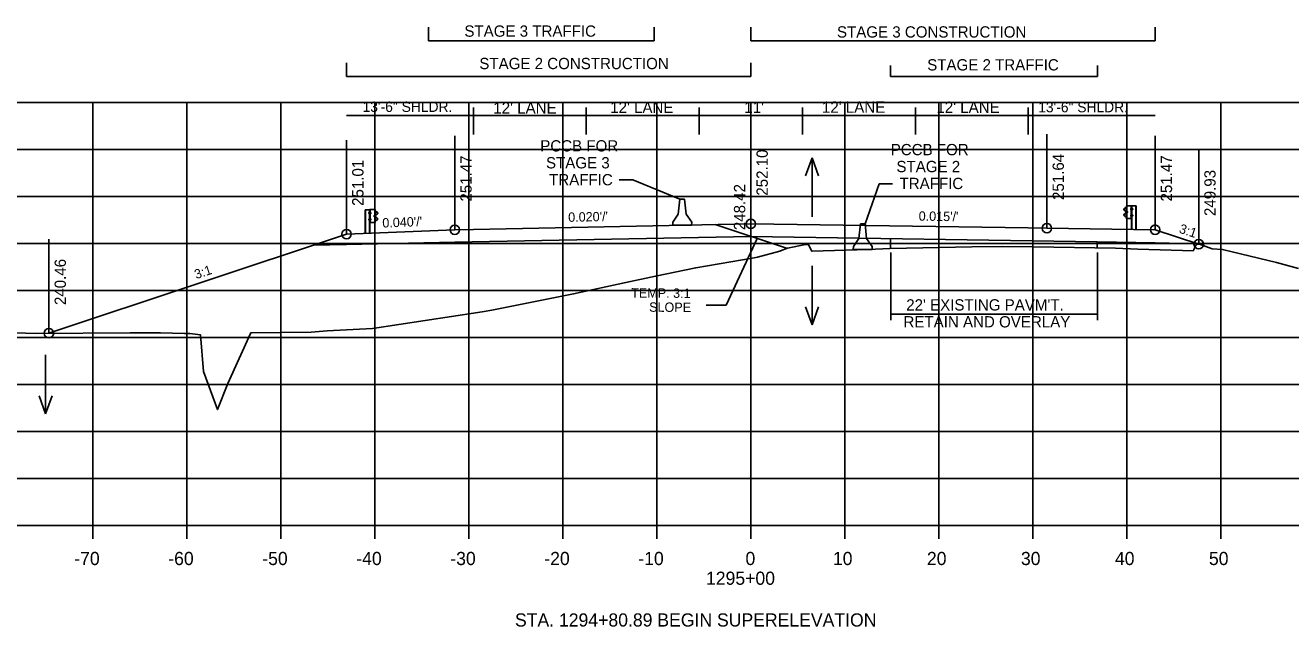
# Model space of a CAD drawing. Extents: x 1342547 to 1344156, y -1532351 to -1517216.
# Drawn here: x 1342625.7 to 1342760.3, y -1520821.7 to -1520757.7 of the extents above; entities that cross this region are included whole.
import ezdxf

# ---------------------------------------------------------------- set-up
doc = ezdxf.new("R2010")
doc.units = 0
for name, color, linetype in [('R_Alt Surface', 7, 'Continuous'), ('R_Axis', 7, 'Continuous'), ('R_Axis Annot', 7, 'Continuous'), ('R_Draft', 7, 'Continuous'), ('R_Exist Surface', 7, 'Continuous'), ('R_Fin Surface', 7, 'Continuous'), ('R_Grid', 7, 'Continuous'), ('R_MOT', 7, 'Continuous'), ('R_No Plot', 7, 'Continuous'), ('R_Water', 7, 'Continuous'), ('R_Xsect Elev', 7, 'Continuous'), ('R_Xsect Slope', 7, 'Continuous')]:
    doc.layers.add(name, color=color, linetype=linetype)

msp = doc.modelspace()

# ---------------------------------------------------------------- linework, layer by layer
at = {"layer": 'R_Alt Surface'}
msp.add_line((1342739.71, -1520780.7), (1342702.87, -1520780.13), dxfattribs=at)
for points in [[(1342659.87, -1520780.99), (1342671.37, -1520780.76), (1342702.87, -1520780.13)], [(1342745.87, -1520780.82), (1342739.71, -1520780.7)], [(1342745.87, -1520780.82), (1342750.33, -1520780.91)], [(1342656.34, -1520781.06), (1342659.87, -1520780.99)]]:
    msp.add_lwpolyline(points, dxfattribs=at)
at = {"layer": 'R_Axis'}
for p, q in [((1342562.87, -1520810.9), (1342842.87, -1520810.9)), ((1342632.87, -1520812.3), (1342632.87, -1520810.9)), ((1342642.87, -1520812.3), (1342642.87, -1520810.9)), ((1342652.87, -1520812.3), (1342652.87, -1520810.9)), ((1342662.87, -1520812.3), (1342662.87, -1520810.9)), ((1342672.87, -1520812.3), (1342672.87, -1520810.9)), ((1342682.87, -1520812.3), (1342682.87, -1520810.9)), ((1342692.87, -1520812.3), (1342692.87, -1520810.9)), ((1342702.87, -1520812.3), (1342702.87, -1520810.9)), ((1342712.87, -1520812.3), (1342712.87, -1520810.9)), ((1342722.87, -1520812.3), (1342722.87, -1520810.9)), ((1342732.87, -1520812.3), (1342732.87, -1520810.9)), ((1342742.87, -1520812.3), (1342742.87, -1520810.9)), ((1342752.87, -1520812.3), (1342752.87, -1520810.9))]:
    msp.add_line(p, q, dxfattribs=at)
at = {"layer": 'R_Draft'}
for p, q in [((1342668.58, -1520759.31), (1342668.58, -1520757.88)), ((1342692.58, -1520759.31), (1342692.58, -1520757.88)), ((1342702.87, -1520759.31), (1342702.87, -1520757.88)), ((1342745.87, -1520759.31), (1342745.87, -1520757.88)), ((1342692.58, -1520759.31), (1342668.58, -1520759.31)), ((1342745.87, -1520759.31), (1342702.87, -1520759.31)), ((1342659.86, -1520763.11), (1342659.86, -1520761.67)), ((1342702.87, -1520763.11), (1342702.87, -1520761.67)), ((1342717.73, -1520763.11), (1342717.73, -1520761.96)), ((1342739.73, -1520763.11), (1342739.73, -1520761.96)), ((1342702.87, -1520763.11), (1342659.86, -1520763.11)), ((1342739.73, -1520763.11), (1342717.73, -1520763.11)), ((1342661.86, -1520777.29), (1342661.86, -1520779.8)), ((1342661.89, -1520777.29), (1342661.89, -1520779.8)), ((1342662.31, -1520777.59), (1342662.26, -1520777.59)), ((1342662.26, -1520777.7), (1342662.26, -1520777.6)), ((1342662.31, -1520777.62), (1342662.26, -1520777.62)), ((1342662.31, -1520777.68), (1342662.26, -1520777.68)), ((1342662.31, -1520777.71), (1342662.26, -1520777.71)), ((1342662.31, -1520777.68), (1342662.27, -1520777.68)), ((1342662.38, -1520777.28), (1342662.31, -1520777.29)), ((1342662.31, -1520777.71), (1342662.31, -1520777.59)), ((1342662.35, -1520779.8), (1342662.35, -1520777.28)), ((1342662.38, -1520777.28), (1342662.38, -1520777.28)), ((1342662.44, -1520777.65), (1342662.38, -1520777.65)), ((1342662.39, -1520777.59), (1342662.44, -1520777.59)), ((1342662.39, -1520777.72), (1342662.44, -1520777.72)), ((1342662.44, -1520777.59), (1342662.44, -1520777.72)), ((1342662.81, -1520778.02), (1342662.81, -1520777.92)), ((1342662.87, -1520777.91), (1342662.82, -1520777.91)), ((1342662.87, -1520777.94), (1342662.82, -1520777.94)), ((1342662.87, -1520778), (1342662.82, -1520778)), ((1342662.87, -1520778.03), (1342662.82, -1520778.03)), ((1342662.87, -1520778), (1342662.83, -1520778)), ((1342662.87, -1520778.03), (1342662.87, -1520777.91)), ((1342662.88, -1520778.65), (1342662.88, -1520777.29)), ((1342663.03, -1520777.5), (1342662.91, -1520777.44)), ((1342663.01, -1520777.52), (1342662.92, -1520777.47)), ((1342662.92, -1520778.03), (1342662.92, -1520777.9)), ((1342662.94, -1520778.03), (1342662.95, -1520777.9)), ((1342663.12, -1520778.2), (1342662.96, -1520778.11)), ((1342662.97, -1520777.83), (1342663.14, -1520777.73)), ((1342662.98, -1520777.85), (1342663.15, -1520777.75)), ((1342663.13, -1520778.18), (1342662.98, -1520778.09)), ((1342663.14, -1520777.62), (1342663.01, -1520777.52)), ((1342663.16, -1520777.6), (1342663.03, -1520777.5)), ((1342742.57, -1520777.19), (1342742.7, -1520777.08)), ((1342742.74, -1520777.44), (1342742.57, -1520777.33)), ((1342742.69, -1520778.03), (1342742.57, -1520777.92)), ((1342742.58, -1520777.2), (1342742.71, -1520777.1)), ((1342742.76, -1520777.41), (1342742.58, -1520777.31)), ((1342742.71, -1520778.02), (1342742.58, -1520777.91)), ((1342742.59, -1520777.77), (1342742.75, -1520777.67)), ((1342742.61, -1520777.79), (1342742.76, -1520777.69)), ((1342742.81, -1520778.09), (1342742.69, -1520778.03)), ((1342742.7, -1520777.08), (1342742.81, -1520777.02)), ((1342742.71, -1520777.1), (1342742.8, -1520777.05)), ((1342742.81, -1520778.07), (1342742.71, -1520778.02)), ((1342742.78, -1520777.62), (1342742.78, -1520777.48)), ((1342742.8, -1520777.61), (1342742.8, -1520777.48)), ((1342742.84, -1520778.23), (1342742.84, -1520776.87)), ((1342742.85, -1520777.62), (1342742.85, -1520777.49)), ((1342742.85, -1520777.49), (1342742.9, -1520777.49)), ((1342742.85, -1520777.52), (1342742.9, -1520777.52)), ((1342742.85, -1520777.59), (1342742.9, -1520777.59)), ((1342742.85, -1520777.59), (1342742.9, -1520777.59)), ((1342742.85, -1520777.62), (1342742.9, -1520777.62)), ((1342742.91, -1520777.6), (1342742.91, -1520777.51)), ((1342743.33, -1520777.17), (1342743.28, -1520777.17)), ((1342743.28, -1520777.17), (1342743.28, -1520777.3)), ((1342743.33, -1520777.3), (1342743.28, -1520777.3)), ((1342743.28, -1520777.98), (1342743.28, -1520777.86)), ((1342743.28, -1520777.86), (1342743.33, -1520777.86)), ((1342743.28, -1520777.98), (1342743.33, -1520777.98)), ((1342743.29, -1520777.24), (1342743.34, -1520777.24)), ((1342743.29, -1520777.92), (1342743.34, -1520777.92)), ((1342743.34, -1520776.87), (1342743.35, -1520776.87)), ((1342743.34, -1520776.87), (1342743.41, -1520776.87)), ((1342743.37, -1520779.38), (1342743.37, -1520776.87)), ((1342743.41, -1520777.29), (1342743.41, -1520777.17)), ((1342743.41, -1520777.17), (1342743.46, -1520777.17)), ((1342743.41, -1520777.2), (1342743.46, -1520777.2)), ((1342743.41, -1520777.26), (1342743.45, -1520777.26)), ((1342743.41, -1520777.26), (1342743.46, -1520777.26)), ((1342743.41, -1520777.29), (1342743.46, -1520777.29)), ((1342743.42, -1520777.98), (1342743.42, -1520777.86)), ((1342743.42, -1520777.86), (1342743.47, -1520777.86)), ((1342743.42, -1520777.89), (1342743.47, -1520777.89)), ((1342743.42, -1520777.95), (1342743.46, -1520777.95)), ((1342743.42, -1520777.95), (1342743.47, -1520777.95)), ((1342743.42, -1520777.98), (1342743.47, -1520777.98)), ((1342743.47, -1520777.28), (1342743.47, -1520777.18)), ((1342743.48, -1520777.97), (1342743.48, -1520777.87)), ((1342743.84, -1520776.87), (1342743.84, -1520779.38)), ((1342743.87, -1520776.87), (1342743.87, -1520779.38)), ((1342662.3, -1520778.28), (1342662.25, -1520778.28)), ((1342662.25, -1520778.39), (1342662.25, -1520778.29)), ((1342662.3, -1520778.31), (1342662.25, -1520778.31)), ((1342662.3, -1520778.37), (1342662.25, -1520778.37)), ((1342662.3, -1520778.4), (1342662.25, -1520778.4)), ((1342662.3, -1520778.37), (1342662.26, -1520778.37)), ((1342662.3, -1520778.4), (1342662.3, -1520778.28)), ((1342662.38, -1520778.65), (1342662.35, -1520778.65)), ((1342662.44, -1520778.34), (1342662.38, -1520778.34)), ((1342662.44, -1520778.28), (1342662.39, -1520778.28)), ((1342662.44, -1520778.4), (1342662.39, -1520778.4)), ((1342662.44, -1520778.4), (1342662.44, -1520778.28)), ((1342662.91, -1520778.49), (1342663.02, -1520778.43)), ((1342662.92, -1520778.51), (1342663.03, -1520778.45)), ((1342663.02, -1520778.43), (1342663.14, -1520778.33)), ((1342663.03, -1520778.45), (1342663.16, -1520778.34)), ((1342699.09, -1520778.87), (1342706.68, -1520781.4)), ((1342743.34, -1520778.23), (1342743.38, -1520778.23)), ((1342717.71, -1520780.35), (1342717.71, -1520781.42)), ((1342739.71, -1520780.7), (1342739.71, -1520781.35)), ((1342717.76, -1520781.86), (1342717.76, -1520789.06)), ((1342739.76, -1520781.86), (1342739.76, -1520789.06)), ((1342717.76, -1520788.39), (1342739.76, -1520788.39))]:
    msp.add_line(p, q, dxfattribs=at)
for points in [[(1342688.88, -1520774.11), (1342690.32, -1520774.11)], [(1342690.32, -1520774.11), (1342695.32, -1520776.19)], [(1342716.51, -1520774.53), (1342715.02, -1520778.79)], [(1342716.51, -1520774.53), (1342717.95, -1520774.53)], [(1342661.86, -1520777.29), (1342662.31, -1520777.29), (1342662.31, -1520779.8)], [(1342743.87, -1520776.87), (1342743.41, -1520776.87), (1342743.41, -1520779.38)]]:
    msp.add_lwpolyline(points, dxfattribs=at)
for points in [[(1342662.26, -1520777.62), (1342662.26, -1520777.68), (1342662.23, -1520777.68), (1342662.23, -1520777.62)], [(1342662.31, -1520777.57), (1342662.31, -1520777.73), (1342662.32, -1520777.73), (1342662.32, -1520777.57)], [(1342662.91, -1520777.28), (1342662.91, -1520778.65), (1342662.38, -1520778.65), (1342662.38, -1520777.28)], [(1342662.44, -1520777.59), (1342662.44, -1520777.72), (1342662.38, -1520777.72), (1342662.38, -1520777.59)], [(1342662.81, -1520777.94), (1342662.81, -1520778), (1342662.79, -1520778), (1342662.79, -1520777.94)], [(1342662.87, -1520777.89), (1342662.87, -1520778.06), (1342662.88, -1520778.06), (1342662.88, -1520777.89)], [(1342742.82, -1520776.87), (1342742.82, -1520778.23), (1342743.34, -1520778.23), (1342743.34, -1520776.87)], [(1342742.86, -1520777.47), (1342742.86, -1520777.64), (1342742.85, -1520777.64), (1342742.85, -1520777.47)], [(1342742.91, -1520777.52), (1342742.91, -1520777.58), (1342742.94, -1520777.58), (1342742.94, -1520777.52)], [(1342743.29, -1520777.17), (1342743.29, -1520777.3), (1342743.34, -1520777.3), (1342743.34, -1520777.17)], [(1342743.29, -1520777.86), (1342743.29, -1520777.98), (1342743.34, -1520777.98), (1342743.34, -1520777.86)], [(1342743.41, -1520777.15), (1342743.41, -1520777.32), (1342743.4, -1520777.32), (1342743.4, -1520777.15)], [(1342743.42, -1520777.84), (1342743.42, -1520778.01), (1342743.41, -1520778.01), (1342743.41, -1520777.84)], [(1342743.47, -1520777.2), (1342743.47, -1520777.26), (1342743.49, -1520777.26), (1342743.49, -1520777.2)], [(1342743.48, -1520777.89), (1342743.48, -1520777.95), (1342743.5, -1520777.95), (1342743.5, -1520777.89)], [(1342662.24, -1520778.31), (1342662.24, -1520778.37), (1342662.22, -1520778.37), (1342662.22, -1520778.31)], [(1342662.3, -1520778.26), (1342662.3, -1520778.42), (1342662.31, -1520778.42), (1342662.31, -1520778.26)], [(1342662.44, -1520778.28), (1342662.44, -1520778.4), (1342662.38, -1520778.4), (1342662.38, -1520778.28)]]:
    msp.add_lwpolyline(points, close=True, dxfattribs=at)
for centre, radius, start, end in [((1342662.28, -1520777.6), 0.022, 134.5745, 222.2244), ((1342662.35, -1520777.65), 0.0922, 159.7423, 200.2577), ((1342662.28, -1520777.7), 0.025, 140.9334, 216.6234), ((1342662.84, -1520777.92), 0.022, 134.5745, 222.2244), ((1342662.91, -1520777.97), 0.0922, 159.7423, 200.2577), ((1342662.84, -1520778.02), 0.025, 140.9334, 216.6234), ((1342663.01, -1520777.91), 0.0865, 118.106, 175.0444), ((1342662.99, -1520778.04), 0.0703, 171.7804, 246.8536), ((1342662.94, -1520777.97), 0.0453, 282.9554, 86.0697), ((1342662.99, -1520778.04), 0.0462, 171.7804, 246.8536), ((1342663.01, -1520777.91), 0.0622, 118.106, 175.0444), ((1342663.11, -1520777.67), 0.062, 299.2499, 57.9783), ((1342663.11, -1520777.67), 0.0856, 299.2499, 57.9783), ((1342742.61, -1520777.26), 0.0856, 122.0217, 240.7501), ((1342742.65, -1520777.86), 0.109, 120.88, 214.7816), ((1342742.61, -1520777.26), 0.062, 122.0217, 240.7501), ((1342742.65, -1520777.86), 0.0854, 120.88, 214.7816), ((1342742.71, -1520777.49), 0.0622, 4.9556, 61.894), ((1342742.78, -1520777.56), 0.0453, 93.9303, 257.0446), ((1342742.73, -1520777.62), 0.0462, 293.1464, 8.2196), ((1342742.71, -1520777.49), 0.0865, 4.9556, 61.894), ((1342742.73, -1520777.62), 0.0703, 293.1464, 8.2196), ((1342742.89, -1520777.51), 0.022, 317.7756, 45.4255), ((1342742.82, -1520777.55), 0.0922, 339.7423, 20.2577), ((1342742.88, -1520777.6), 0.025, 323.3766, 39.0666), ((1342743.44, -1520777.19), 0.022, 317.7756, 45.4255), ((1342743.37, -1520777.23), 0.0922, 339.7423, 20.2577), ((1342743.44, -1520777.28), 0.025, 323.3766, 39.0666), ((1342743.45, -1520777.87), 0.022, 317.7756, 45.4255), ((1342743.38, -1520777.92), 0.0922, 339.7423, 20.2577), ((1342743.45, -1520777.97), 0.025, 323.3766, 39.0666), ((1342662.27, -1520778.29), 0.022, 134.5745, 222.2244), ((1342662.34, -1520778.34), 0.0922, 159.7423, 200.2577), ((1342662.27, -1520778.39), 0.025, 140.9334, 216.6234), ((1342663.07, -1520778.28), 0.0854, 325.2184, 59.12), ((1342663.07, -1520778.28), 0.109, 325.2184, 59.12)]:
    msp.add_arc(centre, radius, start, end, dxfattribs=at)
at = {"layer": 'R_Exist Surface'}
msp.add_lwpolyline([(1342621.24, -1520790.3), (1342626.8, -1520790.45), (1342636.83, -1520790.38), (1342640.06, -1520790.38), (1342642.61, -1520790.47), (1342643.21, -1520790.46), (1342644.32, -1520790.6), (1342644.65, -1520794.51), (1342646.12, -1520798.55), (1342647.23, -1520795.78), (1342649.65, -1520790.47), (1342649.66, -1520790.4), (1342649.67, -1520790.4), (1342649.75, -1520790.4), (1342656.11, -1520790.33), (1342657.79, -1520790.19), (1342662.64, -1520789.93), (1342673.82, -1520788.24), (1342674.5, -1520788.14), (1342675.31, -1520787.98), (1342684.01, -1520786.25), (1342689.56, -1520785.05), (1342692.73, -1520784.38), (1342697.01, -1520783.47), (1342703.22, -1520782.41), (1342703.59, -1520782.34), (1342705.97, -1520781.7), (1342706.04, -1520781.67), (1342706.76, -1520781.39), (1342708.69, -1520781.01), (1342708.88, -1520781.01), (1342708.99, -1520781.01), (1342709.29, -1520781.59), (1342709.36, -1520781.72), (1342709.36, -1520781.72), (1342715.36, -1520781.52), (1342717.68, -1520781.42), (1342726.39, -1520781.26), (1342729.62, -1520781.2), (1342732.89, -1520781.24), (1342741.67, -1520781.39), (1342744.04, -1520781.48), (1342749.94, -1520781.66), (1342750, -1520781.53), (1342750.28, -1520780.97), (1342750.39, -1520780.97), (1342750.58, -1520780.97), (1342751.96, -1520781.46), (1342753.06, -1520781.54), (1342758.79, -1520782.91), (1342761.14, -1520783.54)], dxfattribs=at)
at = {"layer": 'R_Fin Surface'}
msp.add_lwpolyline([(1342628.21, -1520790.44), (1342659.86, -1520779.89), (1342659.87, -1520779.89), (1342671.37, -1520779.43), (1342673.37, -1520779.39), (1342702.87, -1520778.8), (1342732.37, -1520779.23), (1342734.37, -1520779.26), (1342745.87, -1520779.42), (1342745.88, -1520779.42), (1342750.51, -1520780.97)], dxfattribs=at)
at = {"layer": 'R_Grid'}
for p, q in [((1342562.87, -1520765.9), (1342842.87, -1520765.9)), ((1342632.87, -1520810.9), (1342632.87, -1520765.9)), ((1342642.87, -1520810.9), (1342642.87, -1520765.9)), ((1342652.87, -1520810.9), (1342652.87, -1520765.9)), ((1342662.87, -1520810.9), (1342662.87, -1520765.9)), ((1342672.87, -1520810.9), (1342672.87, -1520765.9)), ((1342682.87, -1520810.9), (1342682.87, -1520765.9)), ((1342692.87, -1520810.9), (1342692.87, -1520765.9)), ((1342702.87, -1520810.9), (1342702.87, -1520765.9)), ((1342712.87, -1520810.9), (1342712.87, -1520765.9)), ((1342722.87, -1520810.9), (1342722.87, -1520765.9)), ((1342732.87, -1520810.9), (1342732.87, -1520765.9)), ((1342742.87, -1520810.9), (1342742.87, -1520765.9)), ((1342752.87, -1520810.9), (1342752.87, -1520765.9)), ((1342562.87, -1520770.9), (1342842.87, -1520770.9)), ((1342562.87, -1520775.9), (1342842.87, -1520775.9)), ((1342562.87, -1520780.9), (1342842.87, -1520780.9)), ((1342562.87, -1520785.9), (1342842.87, -1520785.9)), ((1342562.87, -1520790.9), (1342842.87, -1520790.9)), ((1342562.87, -1520795.9), (1342842.87, -1520795.9)), ((1342562.87, -1520800.9), (1342842.87, -1520800.9)), ((1342562.87, -1520805.9), (1342842.87, -1520805.9)), ((1342562.87, -1520810.9), (1342842.87, -1520810.9))]:
    msp.add_line(p, q, dxfattribs=at)
at = {"layer": 'R_MOT'}
for p, q in [((1342695.15, -1520777.78), (1342695.32, -1520776.19)), ((1342695.57, -1520776.19), (1342695.32, -1520776.19)), ((1342695.82, -1520776.19), (1342695.57, -1520776.19)), ((1342695.99, -1520777.78), (1342695.82, -1520776.19)), ((1342694.58, -1520778.61), (1342695.15, -1520777.78)), ((1342696.58, -1520778.61), (1342695.99, -1520777.78)), ((1342694.57, -1520778.94), (1342694.58, -1520778.61)), ((1342696.57, -1520778.94), (1342694.57, -1520778.94)), ((1342696.57, -1520778.94), (1342696.58, -1520778.61)), ((1342714.36, -1520780.37), (1342714.52, -1520778.79)), ((1342714.77, -1520778.79), (1342714.52, -1520778.79)), ((1342715.02, -1520778.79), (1342714.77, -1520778.79)), ((1342715.19, -1520780.37), (1342715.02, -1520778.79)), ((1342713.78, -1520781.21), (1342714.36, -1520780.37)), ((1342715.78, -1520781.21), (1342715.19, -1520780.37)), ((1342713.77, -1520781.54), (1342713.78, -1520781.21)), ((1342715.78, -1520781.54), (1342713.77, -1520781.54)), ((1342715.78, -1520781.54), (1342715.78, -1520781.21))]:
    msp.add_line(p, q, dxfattribs=at)
at = {"layer": 'R_No Plot'}
for centre in [(1342659.86, -1520779.89), (1342659.87, -1520779.89), (1342671.37, -1520779.43), (1342702.87, -1520778.8), (1342734.37, -1520779.26), (1342745.87, -1520779.42), (1342745.88, -1520779.42), (1342750.51, -1520780.97), (1342628.21, -1520790.44)]:
    msp.add_circle(centre, 0.5, dxfattribs=at)
at = {"layer": 'R_Water'}
for p, q in [((1342709.38, -1520771.76), (1342708.68, -1520773.69)), ((1342709.38, -1520778.05), (1342709.38, -1520771.76)), ((1342709.38, -1520771.76), (1342710.08, -1520773.69)), ((1342709.38, -1520783.25), (1342709.38, -1520789.53)), ((1342709.38, -1520789.53), (1342708.68, -1520787.61)), ((1342709.38, -1520789.53), (1342710.08, -1520787.61)), ((1342627.85, -1520792.73), (1342627.85, -1520799.02)), ((1342627.85, -1520799.02), (1342627.15, -1520797.09)), ((1342627.85, -1520799.02), (1342628.55, -1520797.09))]:
    msp.add_line(p, q, dxfattribs=at)
at = {"layer": 'R_Xsect Elev'}
for p, q in [((1342745.88, -1520767.27), (1342659.87, -1520767.27)), ((1342673.37, -1520769.28), (1342673.37, -1520766.42)), ((1342685.37, -1520769.28), (1342685.37, -1520766.42)), ((1342697.37, -1520769.28), (1342697.37, -1520766.42)), ((1342708.37, -1520769.28), (1342708.37, -1520766.42)), ((1342720.37, -1520769.28), (1342720.37, -1520766.42)), ((1342732.37, -1520769.28), (1342732.37, -1520766.42)), ((1342659.86, -1520779.89), (1342659.86, -1520769.89)), ((1342659.87, -1520779.89), (1342659.87, -1520769.89)), ((1342671.37, -1520779.43), (1342671.37, -1520769.43)), ((1342702.87, -1520778.8), (1342702.87, -1520768.8)), ((1342734.37, -1520779.26), (1342734.37, -1520769.26)), ((1342745.87, -1520779.42), (1342745.87, -1520769.42)), ((1342745.88, -1520779.42), (1342745.88, -1520769.42)), ((1342750.51, -1520780.97), (1342750.51, -1520770.97)), ((1342702.87, -1520782.47), (1342702.87, -1520772.47)), ((1342628.21, -1520790.44), (1342628.21, -1520780.44)), ((1342703.55, -1520780.36), (1342700.25, -1520787.44)), ((1342700.25, -1520787.44), (1342698.11, -1520787.44))]:
    msp.add_line(p, q, dxfattribs=at)

# ---------------------------------------------------------------- texts
at = {"layer": 'R_Axis Annot'}
for s, p in [('-70', (1342630.9, -1520815.1)), ('-60', (1342640.9, -1520815.1)), ('-50', (1342650.9, -1520815.1)), ('-40', (1342660.9, -1520815.1)), ('-30', (1342670.9, -1520815.1)), ('-20', (1342680.9, -1520815.1)), ('-10', (1342690.9, -1520815.1)), ('0', (1342702.3, -1520815.1)), ('10', (1342711.6, -1520815.1)), ('20', (1342721.6, -1520815.1)), ('30', (1342731.6, -1520815.1)), ('40', (1342741.6, -1520815.1)), ('50', (1342751.6, -1520815.1)), ('1295+00', (1342698.1, -1520817.2)), ('STA. 1294+80.89 BEGIN SUPERELEVATION', (1342677.78, -1520821.64))]:
    msp.add_text(s, height=1.4, dxfattribs=at).set_placement(p)
at = {"layer": 'R_Draft'}
for s, p in [('STAGE 3 TRAFFIC', (1342672.4, -1520758.89)), ('STAGE 3 CONSTRUCTION', (1342712.03, -1520758.98)), ('STAGE 2 CONSTRUCTION', (1342673.99, -1520762.34)), ('STAGE 2 TRAFFIC', (1342721.63, -1520762.48)), ('PCCB FOR', (1342680.47, -1520771.1)), ('PCCB FOR', (1342717.75, -1520771.5)), ('STAGE 3', (1342681.08, -1520772.9)), ('STAGE 2', (1342718.36, -1520773.3)), ('TRAFFIC', (1342681.41, -1520774.7)), ('TRAFFIC', (1342718.69, -1520775.1)), ("22' EXISTING PAVM'T.", (1342719.4, -1520788.02)), ('RETAIN AND OVERLAY', (1342719.11, -1520789.82))]:
    msp.add_text(s, height=1.2, dxfattribs=at).set_placement(p)
at = {"layer": 'R_Xsect Elev'}
for s, height, p in [('13\'-6" SHLDR.', 1.1, (1342661.57, -1520766.89)), ("12' LANE", 1.2, (1342675.48, -1520767.06)), ("12' LANE", 1.2, (1342687.91, -1520767.01)), ("11'", 1.2, (1342702.18, -1520767.01)), ("12' LANE", 1.2, (1342710.44, -1520766.98)), ("12' LANE", 1.2, (1342722.61, -1520766.99)), ('13\'-6" SHLDR.', 1.1, (1342733.44, -1520766.93))]:
    msp.add_text(s, height=height, dxfattribs=at).set_placement(p)
for s, p in [('252.10', (1342704.67, -1520775.8)), ('251.64', (1342736.17, -1520776.26)), ('251.01', (1342661.66, -1520776.89)), ('251.01', (1342661.67, -1520776.89)), ('251.47', (1342673.17, -1520776.43)), ('251.47', (1342747.67, -1520776.42)), ('251.47', (1342747.68, -1520776.42)), ('249.93', (1342752.31, -1520777.97)), ('248.42', (1342702.27, -1520779.47)), ('240.46', (1342630.01, -1520787.44))]:
    msp.add_text(s, height=1.2, rotation=90, dxfattribs=at).set_placement(p)
at = {"layer": 'R_Xsect Slope'}
for s, rotation, p in [("0.040'/'", 2.2906, (1342663.69, -1520779.2)), ("0.020'/'", 1.1458, (1342683.45, -1520778.59)), ("0.015'/'", 359.1664, (1342720.72, -1520778.46)), ('3:1', 341.5651, (1342748.35, -1520779.72)), ('3:1', 18.4349, (1342643.87, -1520784.69)), ('TEMP. 3:1', 359.6242, (1342690.14, -1520786.64)), ('SLOPE', 359.6242, (1342692.05, -1520788.15))]:
    msp.add_text(s, height=1, rotation=rotation, dxfattribs=at).set_placement(p)

doc.saveas('drawing.dxf')
